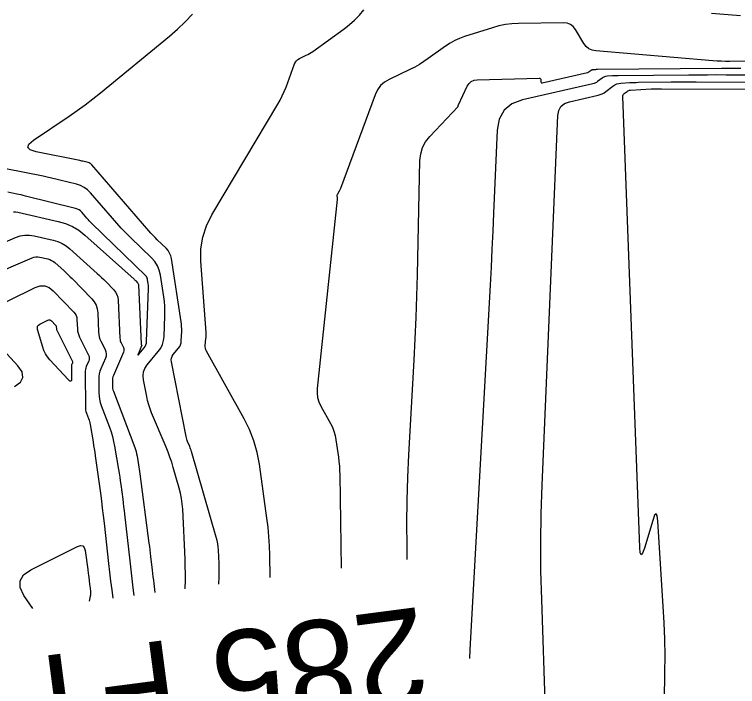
# Model space of a CAD drawing. Extents: x 1768942 to 1774819, y 723037 to 732099.
# Drawn here: x 1770771.97 to 1770816.88, y 724743.06 to 724784.79 of the extents above; entities that cross this region are included whole.
import ezdxf

# ---------------------------------------------------------------- set-up
doc = ezdxf.new("R2010")
doc.units = 0
doc.layers.add('R_Contour Annot', color=7, linetype='Continuous')
doc.layers.add('R_Contours', color=7, linetype='Continuous')

msp = doc.modelspace()

# ---------------------------------------------------------------- linework, layer by layer
at = {"layer": 'R_Contours'}
for points in [[(1770784.666, 724749.409), (1770784.683, 724749.867), (1770784.689, 724750.073), (1770784.69, 724750.28), (1770784.687, 724750.487), (1770784.68, 724750.693), (1770784.642, 724751.52), (1770784.627, 724751.726), (1770784.599, 724751.93), (1770784.56, 724752.131), (1770784.508, 724752.331), (1770782.965, 724757.656), (1770782.941, 724757.734), (1770782.915, 724757.812), (1770782.887, 724757.888), (1770782.856, 724757.964), (1770782.729, 724758.266), (1770782.7, 724758.343), (1770782.674, 724758.42), (1770782.652, 724758.499), (1770782.634, 724758.578), (1770781.717, 724763.219), (1770781.706, 724763.342), (1770781.721, 724763.458), (1770781.763, 724763.568), (1770781.832, 724763.67), (1770782.163, 724764.067), (1770782.235, 724764.17), (1770782.289, 724764.28), (1770782.323, 724764.398), (1770782.337, 724764.523), (1770782.36, 724765.135), (1770782.362, 724765.28), (1770782.357, 724765.424), (1770782.345, 724765.568), (1770782.326, 724765.712), (1770781.72, 724769.631), (1770781.678, 724769.811), (1770781.609, 724769.978), (1770781.513, 724770.131), (1770781.39, 724770.27), (1770780.846, 724770.799), (1770780.711, 724770.932), (1770780.58, 724771.069), (1770780.451, 724771.208), (1770780.326, 724771.35), (1770776.774, 724775.46), (1770776.727, 724775.507), (1770776.675, 724775.544), (1770776.618, 724775.574), (1770776.556, 724775.594), (1770776.294, 724775.659), (1770776.229, 724775.675), (1770776.163, 724775.69), (1770776.098, 724775.705), (1770776.032, 724775.718), (1770773.314, 724776.262), (1770772.949, 724776.379), (1770772.802, 724776.54), (1770772.875, 724776.745), (1770773.167, 724776.994), (1770775.372, 724778.483), (1770775.869, 724778.827), (1770776.357, 724779.182), (1770776.838, 724779.549), (1770777.31, 724779.926), (1770781.605, 724783.446), (1770782.103, 724783.875), (1770782.58, 724784.326), (1770783.034, 724784.8)], [(1770787.853, 724749.826), (1770787.831, 724751.214), (1770787.813, 724751.793), (1770787.777, 724752.37), (1770787.724, 724752.945), (1770787.653, 724753.519), (1770787.186, 724756.864), (1770787.049, 724757.601), (1770786.846, 724758.317), (1770786.577, 724759.01), (1770786.242, 724759.681), (1770783.9, 724763.882), (1770783.859, 724763.97), (1770783.833, 724764.062), (1770783.821, 724764.156), (1770783.824, 724764.253), (1770783.866, 724764.649), (1770783.874, 724764.748), (1770783.878, 724764.847), (1770783.877, 724764.946), (1770783.872, 724765.045), (1770783.553, 724769.475), (1770783.553, 724770.233), (1770783.667, 724770.964), (1770783.894, 724771.668), (1770784.233, 724772.346), (1770788.33, 724779.218), (1770788.476, 724779.475), (1770788.609, 724779.739), (1770788.73, 724780.008), (1770788.839, 724780.283), (1770789.373, 724781.729), (1770789.422, 724781.833), (1770789.488, 724781.921), (1770789.57, 724781.994), (1770789.668, 724782.052), (1770790.096, 724782.255), (1770790.202, 724782.307), (1770790.304, 724782.365), (1770790.404, 724782.427), (1770790.502, 724782.494), (1770792.439, 724783.893), (1770792.779, 724784.158), (1770793.099, 724784.445), (1770793.397, 724784.753), (1770793.674, 724785.084)], [(1770815.264, 724784.878), (1770817.056, 724784.719)], [(1770817.924, 724781.893), (1770816.394, 724781.879), (1770816.132, 724781.879), (1770815.87, 724781.886), (1770815.608, 724781.899), (1770815.346, 724781.917), (1770808.081, 724782.522), (1770807.848, 724782.567), (1770807.644, 724782.66), (1770807.471, 724782.802), (1770807.328, 724782.992), (1770806.816, 724783.847), (1770806.672, 724784.034), (1770806.499, 724784.167), (1770806.295, 724784.245), (1770806.061, 724784.269), (1770803.282, 724784.232), (1770802.869, 724784.211), (1770802.462, 724784.161), (1770802.059, 724784.08), (1770801.662, 724783.969), (1770799.924, 724783.417), (1770799.613, 724783.305), (1770799.314, 724783.169), (1770799.026, 724783.009), (1770798.751, 724782.826), (1770797.673, 724782.048), (1770797.4, 724781.86), (1770797.118, 724781.685), (1770796.83, 724781.523), (1770796.533, 724781.374), (1770795.239, 724780.762), (1770794.948, 724780.59), (1770794.705, 724780.374), (1770794.511, 724780.113), (1770794.366, 724779.808), (1770792.214, 724773.977), (1770792.198, 724773.935), (1770792.179, 724773.895), (1770792.159, 724773.855), (1770792.137, 724773.815), (1770792.027, 724773.631), (1770792.015, 724773.607), (1770792.007, 724773.581), (1770792.003, 724773.556), (1770792.003, 724773.529), (1770792.01, 724773.419), (1770792.012, 724773.392), (1770792.012, 724773.364), (1770792.011, 724773.337), (1770792.009, 724773.31), (1770790.776, 724761.573), (1770790.767, 724761.284), (1770790.802, 724761.004), (1770790.88, 724760.732), (1770791.002, 724760.47), (1770791.598, 724759.401), (1770791.72, 724759.158), (1770791.817, 724758.906), (1770791.891, 724758.647), (1770791.941, 724758.38), (1770792.092, 724757.295), (1770792.126, 724757.023), (1770792.151, 724756.751), (1770792.168, 724756.478), (1770792.176, 724756.204), (1770792.268, 724750.403)], [(1770796.371, 724750.939), (1770796.357, 724751.767), (1770796.347, 724753.189), (1770796.362, 724754.61), (1770796.403, 724756.031), (1770796.469, 724757.452), (1770796.794, 724763.323), (1770796.862, 724764.648), (1770796.918, 724765.974), (1770796.964, 724767.3), (1770796.999, 724768.626), (1770797.155, 724775.724), (1770797.2, 724776.14), (1770797.317, 724776.527), (1770797.505, 724776.884), (1770797.764, 724777.213), (1770799.523, 724779.084), (1770799.528, 724779.09), (1770799.531, 724779.096), (1770799.533, 724779.103), (1770799.534, 724779.111), (1770799.535, 724779.141), (1770799.535, 724779.149), (1770799.537, 724779.157), (1770799.539, 724779.164), (1770799.542, 724779.171), (1770800.096, 724780.332), (1770800.205, 724780.505), (1770800.345, 724780.629), (1770800.515, 724780.706), (1770800.717, 724780.736), (1770804.566, 724780.84), (1770804.601, 724780.836), (1770804.627, 724780.822), (1770804.644, 724780.798), (1770804.652, 724780.764), (1770804.667, 724780.605), (1770804.675, 724780.572), (1770804.692, 724780.55), (1770804.717, 724780.541), (1770804.752, 724780.544), (1770807.55, 724781.181), (1770807.583, 724781.19), (1770807.615, 724781.203), (1770807.645, 724781.22), (1770807.673, 724781.239), (1770807.784, 724781.325), (1770807.813, 724781.344), (1770807.843, 724781.358), (1770807.876, 724781.368), (1770807.91, 724781.372), (1770808.05, 724781.38), (1770808.085, 724781.382), (1770808.12, 724781.384), (1770808.155, 724781.385), (1770808.191, 724781.385), (1770815.888, 724781.459), (1770816.189, 724781.461), (1770816.489, 724781.462), (1770816.79, 724781.463), (1770817.09, 724781.462)], [(1770818.48, 724781.022), (1770816.166, 724781.03), (1770815.588, 724781.032), (1770815.009, 724781.031), (1770814.431, 724781.028), (1770813.852, 724781.024), (1770809.46, 724780.982), (1770809.374, 724780.98), (1770809.287, 724780.978), (1770809.201, 724780.975), (1770809.115, 724780.97), (1770808.771, 724780.95), (1770808.687, 724780.939), (1770808.608, 724780.916), (1770808.533, 724780.881), (1770808.463, 724780.835), (1770808.191, 724780.624), (1770808.121, 724780.576), (1770808.047, 724780.535), (1770807.969, 724780.504), (1770807.887, 724780.48), (1770803.525, 724779.487), (1770802.861, 724779.24), (1770802.376, 724778.843), (1770802.073, 724778.295), (1770801.95, 724777.597), (1770801.73, 724772.442), (1770801.68, 724771.325), (1770801.627, 724770.208), (1770801.571, 724769.092), (1770801.511, 724767.975), (1770800.258, 724745.356), (1770800.233, 724744.804)], [(1770804.956, 724741.499), (1770804.714, 724748.468), (1770804.669, 724750.242), (1770804.659, 724752.015), (1770804.683, 724753.789), (1770804.742, 724755.562), (1770805.721, 724778.515), (1770805.777, 724778.832), (1770805.914, 724779.08), (1770806.134, 724779.261), (1770806.436, 724779.373), (1770808.224, 724779.78), (1770808.355, 724779.817), (1770808.479, 724779.868), (1770808.597, 724779.931), (1770808.708, 724780.009), (1770809.141, 724780.344), (1770809.253, 724780.419), (1770809.372, 724780.474), (1770809.498, 724780.511), (1770809.632, 724780.528), (1770810.18, 724780.56), (1770810.317, 724780.567), (1770810.454, 724780.572), (1770810.592, 724780.576), (1770810.729, 724780.578), (1770812.76, 724780.598), (1770813.145, 724780.601), (1770813.529, 724780.603), (1770813.913, 724780.603), (1770814.298, 724780.602), (1770819.567, 724780.583)], [(1770812.275, 724737.071), (1770812.37, 724743.931), (1770812.374, 724744.962), (1770812.359, 724745.993), (1770812.322, 724747.023), (1770812.266, 724748.052), (1770811.926, 724753.336), (1770811.885, 724753.673), (1770811.819, 724753.791), (1770811.727, 724753.691), (1770811.611, 724753.372), (1770811.097, 724751.657), (1770810.982, 724751.337), (1770810.895, 724751.237), (1770810.837, 724751.356), (1770810.806, 724751.694), (1770809.758, 724779.687), (1770809.761, 724779.742), (1770809.777, 724779.791), (1770809.805, 724779.835), (1770809.844, 724779.873), (1770810.026, 724780.014), (1770810.073, 724780.045), (1770810.123, 724780.068), (1770810.176, 724780.083), (1770810.232, 724780.091), (1770811.515, 724780.165), (1770811.568, 724780.168), (1770811.621, 724780.17), (1770811.675, 724780.172), (1770811.728, 724780.172), (1770811.942, 724780.174), (1770811.995, 724780.175), (1770812.049, 724780.175), (1770812.102, 724780.175), (1770812.155, 724780.175), (1770820.934, 724780.143)], [(1770782.572, 724749.135), (1770782.574, 724749.183), (1770782.586, 724749.628), (1770782.589, 724750.072), (1770782.583, 724750.517), (1770782.567, 724750.962), (1770782.424, 724754.075), (1770782.399, 724754.407), (1770782.355, 724754.736), (1770782.291, 724755.062), (1770782.208, 724755.384), (1770781.836, 724756.668), (1770781.738, 724756.988), (1770781.632, 724757.304), (1770781.516, 724757.617), (1770781.391, 724757.927), (1770780.494, 724760.064), (1770780.398, 724760.309), (1770780.315, 724760.558), (1770780.245, 724760.811), (1770780.188, 724761.068), (1770779.983, 724762.103), (1770779.959, 724762.355), (1770779.991, 724762.592), (1770780.077, 724762.816), (1770780.218, 724763.026), (1770780.908, 724763.854), (1770781.059, 724764.067), (1770781.17, 724764.296), (1770781.24, 724764.54), (1770781.27, 724764.8), (1770781.317, 724766.069), (1770781.321, 724766.369), (1770781.311, 724766.669), (1770781.287, 724766.967), (1770781.248, 724767.265), (1770781.042, 724768.595), (1770780.97, 724768.904), (1770780.851, 724769.189), (1770780.687, 724769.451), (1770780.477, 724769.689), (1770779.182, 724770.947), (1770778.892, 724771.235), (1770778.609, 724771.53), (1770778.331, 724771.83), (1770778.061, 724772.136), (1770776.693, 724773.719), (1770776.508, 724773.904), (1770776.302, 724774.054), (1770776.075, 724774.17), (1770775.827, 724774.251), (1770774.793, 724774.509), (1770774.534, 724774.572), (1770774.274, 724774.632), (1770774.014, 724774.689), (1770773.753, 724774.743), (1770771.44, 724775.205)], [(1770771.906, 724772.536), (1770772.046, 724772.537), (1770772.188, 724772.516), (1770774.694, 724771.944), (1770775.146, 724771.812), (1770775.57, 724771.626), (1770775.967, 724771.387), (1770776.336, 724771.096), (1770779.401, 724768.354), (1770779.43, 724768.328), (1770779.458, 724768.301), (1770779.486, 724768.274), (1770779.513, 724768.246), (1770779.622, 724768.133), (1770779.646, 724768.104), (1770779.663, 724768.072), (1770779.674, 724768.037), (1770779.679, 724767.999), (1770779.846, 724764.316), (1770779.846, 724764.306), (1770779.848, 724764.297), (1770779.851, 724764.289), (1770779.855, 724764.28), (1770779.871, 724764.247), (1770779.875, 724764.239), (1770779.876, 724764.23), (1770779.875, 724764.222), (1770779.872, 724764.213), (1770779.67, 724763.74), (1770779.646, 724763.677), (1770779.646, 724763.652), (1770779.668, 724763.664), (1770779.713, 724763.713), (1770780.03, 724764.093), (1770780.093, 724764.182), (1770780.139, 724764.278), (1770780.169, 724764.38), (1770780.181, 724764.489), (1770780.303, 724767.776), (1770780.304, 724767.846), (1770780.302, 724767.915), (1770780.296, 724767.984), (1770780.287, 724768.054), (1770780.245, 724768.33), (1770780.229, 724768.396), (1770780.204, 724768.458), (1770780.168, 724768.514), (1770780.123, 724768.565), (1770776.786, 724771.808), (1770776.703, 724771.89), (1770776.621, 724771.975), (1770776.542, 724772.061), (1770776.464, 724772.149), (1770776.156, 724772.505), (1770776.075, 724772.587), (1770775.984, 724772.653), (1770775.884, 724772.704), (1770775.774, 724772.74), (1770772.659, 724773.516), (1770772.523, 724773.549), (1770772.387, 724773.581), (1770772.25, 724773.611), (1770772.113, 724773.639), (1770771.565, 724773.749)], [(1770769.596, 724769.894), (1770772.046, 724770.942), (1770772.326, 724771.037), (1770772.611, 724771.086), (1770772.899, 724771.089), (1770773.192, 724771.045), (1770774.372, 724770.776), (1770774.658, 724770.692), (1770774.927, 724770.575), (1770775.179, 724770.423), (1770775.413, 724770.238), (1770777.121, 724768.71), (1770777.255, 724768.588), (1770777.387, 724768.463), (1770777.516, 724768.336), (1770777.644, 724768.206), (1770778.147, 724767.683), (1770778.258, 724767.546), (1770778.34, 724767.396), (1770778.392, 724767.233), (1770778.415, 724767.058), (1770778.522, 724764.686), (1770778.53, 724764.609), (1770778.545, 724764.534), (1770778.568, 724764.462), (1770778.599, 724764.391), (1770778.738, 724764.113), (1770778.765, 724764.043), (1770778.775, 724763.973), (1770778.769, 724763.902), (1770778.747, 724763.831), (1770778.119, 724762.366), (1770778.091, 724762.29), (1770778.071, 724762.212), (1770778.059, 724762.133), (1770778.056, 724762.052), (1770778.058, 724761.726), (1770778.062, 724761.644), (1770778.073, 724761.565), (1770778.092, 724761.486), (1770778.117, 724761.409), (1770779.442, 724757.907), (1770779.488, 724757.776), (1770779.528, 724757.643), (1770779.56, 724757.509), (1770779.587, 724757.372), (1770779.679, 724756.823), (1770779.701, 724756.686), (1770779.723, 724756.548), (1770779.743, 724756.41), (1770779.761, 724756.272), (1770780.328, 724751.969), (1770780.355, 724751.759), (1770780.381, 724751.55), (1770780.406, 724751.34), (1770780.43, 724751.13), (1770780.524, 724750.29), (1770780.548, 724750.08), (1770780.573, 724749.871), (1770780.599, 724749.661), (1770780.627, 724749.452), (1770780.702, 724748.89)], [(1770767.032, 724767.096), (1770773.068, 724769.678), (1770773.186, 724769.718), (1770773.307, 724769.739), (1770773.428, 724769.74), (1770773.552, 724769.721), (1770774.05, 724769.608), (1770774.171, 724769.573), (1770774.284, 724769.523), (1770774.39, 724769.459), (1770774.489, 724769.381), (1770775.068, 724768.863), (1770775.195, 724768.747), (1770775.32, 724768.629), (1770775.443, 724768.509), (1770775.563, 724768.386), (1770776.775, 724767.126), (1770776.928, 724766.937), (1770777.041, 724766.731), (1770777.113, 724766.506), (1770777.145, 724766.265), (1770777.199, 724765.056), (1770777.213, 724764.911), (1770777.242, 724764.771), (1770777.285, 724764.635), (1770777.343, 724764.502), (1770777.605, 724763.979), (1770777.655, 724763.848), (1770777.674, 724763.715), (1770777.663, 724763.582), (1770777.621, 724763.448), (1770777.339, 724762.792), (1770777.282, 724762.636), (1770777.241, 724762.477), (1770777.217, 724762.314), (1770777.21, 724762.148), (1770777.216, 724761.287), (1770777.226, 724761.089), (1770777.254, 724760.894), (1770777.298, 724760.703), (1770777.36, 724760.515), (1770777.873, 724759.159), (1770777.975, 724758.869), (1770778.062, 724758.575), (1770778.135, 724758.277), (1770778.193, 724757.976), (1770778.437, 724756.527), (1770778.474, 724756.298), (1770778.509, 724756.068), (1770778.543, 724755.838), (1770778.574, 724755.608), (1770778.695, 724754.687), (1770778.725, 724754.457), (1770778.754, 724754.226), (1770778.781, 724753.995), (1770778.807, 724753.765), (1770779.131, 724750.861), (1770779.195, 724750.301), (1770779.263, 724749.741), (1770779.333, 724749.181), (1770779.394, 724748.719)], [(1770769.969, 724766.229), (1770773.258, 724767.832), (1770773.565, 724767.935), (1770773.855, 724767.936), (1770774.126, 724767.836), (1770774.38, 724767.633), (1770775.652, 724766.31), (1770775.737, 724766.205), (1770775.8, 724766.09), (1770775.84, 724765.966), (1770775.858, 724765.831), (1770775.883, 724765.275), (1770775.896, 724765.138), (1770775.923, 724765.004), (1770775.965, 724764.874), (1770776.02, 724764.748), (1770776.577, 724763.633), (1770776.611, 724763.547), (1770776.623, 724763.459), (1770776.616, 724763.372), (1770776.588, 724763.283), (1770776.436, 724762.928), (1770776.403, 724762.839), (1770776.379, 724762.747), (1770776.365, 724762.654), (1770776.361, 724762.558), (1770776.378, 724760.399), (1770776.382, 724760.307), (1770776.395, 724760.216), (1770776.416, 724760.127), (1770776.445, 724760.04), (1770776.576, 724759.693), (1770776.606, 724759.606), (1770776.633, 724759.517), (1770776.655, 724759.428), (1770776.672, 724759.337), (1770776.856, 724758.245), (1770776.89, 724758.033), (1770776.924, 724757.82), (1770776.956, 724757.607), (1770776.986, 724757.394), (1770777.31, 724755.057), (1770777.372, 724754.596), (1770777.431, 724754.135), (1770777.487, 724753.674), (1770777.54, 724753.212), (1770777.821, 724750.696), (1770777.883, 724750.153), (1770777.948, 724749.61), (1770778.016, 724749.068), (1770778.085, 724748.548)], [(1770771.975, 724761.679), (1770772.342, 724761.948), (1770772.5, 724762.252), (1770772.45, 724762.59), (1770772.191, 724762.964), (1770770.158, 724765.157)], [(1770773.107, 724747.897), (1770772.561, 724748.718), (1770772.331, 724749.203), (1770772.324, 724749.628), (1770772.541, 724749.994), (1770772.983, 724750.3), (1770775.899, 724751.754), (1770776.079, 724751.815), (1770776.217, 724751.794), (1770776.313, 724751.692), (1770776.365, 724751.508), (1770776.527, 724750.336), (1770776.539, 724750.251), (1770776.55, 724750.165), (1770776.56, 724750.079), (1770776.57, 724749.994), (1770776.609, 724749.644), (1770776.619, 724749.561), (1770776.629, 724749.479), (1770776.639, 724749.397), (1770776.65, 724749.315), (1770776.694, 724748.986), (1770776.701, 724748.904), (1770776.702, 724748.823), (1770776.695, 724748.741), (1770776.681, 724748.66), (1770776.614, 724748.356)]]:
    msp.add_lwpolyline(points, dxfattribs=at)
msp.add_lwpolyline([(1770774.546, 724765.473), (1770774.559, 724765.45), (1770774.567, 724765.425), (1770774.571, 724765.398), (1770774.576, 724765.286), (1770774.578, 724765.258), (1770774.584, 724765.231), (1770774.592, 724765.205), (1770774.603, 724765.18), (1770775.569, 724763.249), (1770775.578, 724763.227), (1770775.581, 724763.204), (1770775.579, 724763.181), (1770775.572, 724763.158), (1770775.532, 724763.065), (1770775.524, 724763.042), (1770775.518, 724763.018), (1770775.514, 724762.993), (1770775.513, 724762.968), (1770775.519, 724762.173), (1770775.508, 724762.063), (1770775.473, 724762.013), (1770775.413, 724762.025), (1770775.329, 724762.098), (1770774.168, 724763.35), (1770774.023, 724763.526), (1770773.901, 724763.714), (1770773.803, 724763.916), (1770773.728, 724764.131), (1770773.411, 724765.238), (1770773.396, 724765.341), (1770773.415, 724765.429), (1770773.468, 724765.502), (1770773.554, 724765.56), (1770774.048, 724765.8), (1770774.11, 724765.821), (1770774.168, 724765.821), (1770774.222, 724765.801), (1770774.273, 724765.76), (1770774.529, 724765.494)], close=True, dxfattribs=at)

# ---------------------------------------------------------------- texts
at = {"layer": 'R_Contour Annot'}
msp.add_text('285 FT', height=6, rotation=187.45, dxfattribs=at).set_placement((1770797.215, 724748.024))

doc.saveas('drawing.dxf')
